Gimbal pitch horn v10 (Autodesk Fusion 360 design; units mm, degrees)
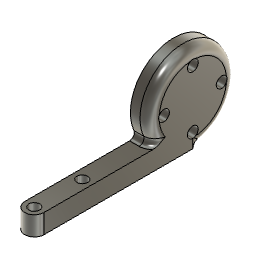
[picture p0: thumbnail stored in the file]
sketch "草图1" plane through (0, 0, 0) normal (1, 0, 0) x axis (0, 1, 0)
  line L1 (0, 6) -> (0, 0)
  circle C1 centre (0, 0) radius 9
  circle C2 centre (0, 6) radius 1.125
  circle C3 centre (-6, 0) radius 1.125
  circle C4 centre (0, -6) radius 1.125
  circle C5 centre (6, 0) radius 1.125
  point P1 (0, 0)
  point P2 (0, 0)
  point P3 (0, 0)
  point P4 (0, 6)
  point P5 (0, 6)
  coincident P1 P2
  coincident P2 P3
  vertical L1
  coincident P4 P5
  dimension "d1" diameter C1 = 18
  dimension "d2" diameter C2 = 2.25
  dimension "d3" distance P3 P4 = 6
  dimension "d5" C-Pattern1-Angle = 360
extrude "拉伸1" new body sketch "草图1" profile of C1 C2 C3 C4 C5 along normal blind 4
sketch "草图2" plane through (0, 0, 0) normal (0, 0, 1) x axis (1, 0, 0)
  line L1 (4, -9) -> (0, -9)
  line L2 (2, -21) -> (2, -9)
  line L3 (0, -33) -> (4, -33)
  line L4 (0, -9) -> (0, -33)
  line L5 (4, -9) -> (0, -9)
  line L6 (4, -33) -> (4, -9)
  line L7 (0, -9) -> (4, -33)
  line L8 (4, -9) -> (0, -33)
  line L9 (4, 9) -> (4, -9)
  line L10 (0, 9) -> (0, -9)
  line L11 (0.0245, -26) -> (4.0245, -26)
  circle C1 centre (2, -21) radius 1.125
  circle C2 centre (2, -31) radius 1.125
  point P4 (2, -9)
  point P10 (2, -21)
  point P5 (2, -21)
  point P3 (4, -9)
  point P11 (4, -9)
  point P17 (2, -21)
  point P6 (4, -33)
  point P7 (0, -33)
  point P9 (4, -9)
  horizontal L1
  midpoint L1 P4
  perpendicular L1 L2
  horizontal L3
  perpendicular L3 L4
  parallel L3 L5
  parallel L4 L6
  coincident L7 P10
  coincident L8 P10
  coincident P5 P10
  collinear L1 L5
  collinear L6 L9
  coincident P3 P11
  coincident L2 P17
  symmetric L11 C1 C2
  dimension "d8" distance P6 P7 = 4
  dimension "d9" distance P6 P9 = 24
  dimension "d17" diameter C1 = 2.25
  dimension "d18" distance L11 P17 = 5
  dimension "d30" distance L3 L11 = 7
extrude "拉伸2" new body sketch "草图2" profile of L1 L3 L4 L5 L6 C1 C2 blind -4 from offset -5 (= "-9.00 mm + 4 mm")
fillet "圆角5" radius 2
extrude "拉伸3" add of existing geometry blind 1
extrude "拉伸4" add of existing geometry blind 8
extrude "拉伸5" cut sketch "草图1" profile of C4 along normal blind 4
fillet "圆角2" radius 1
fillet "圆角6" radius 2
fillet "圆角7" radius 2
